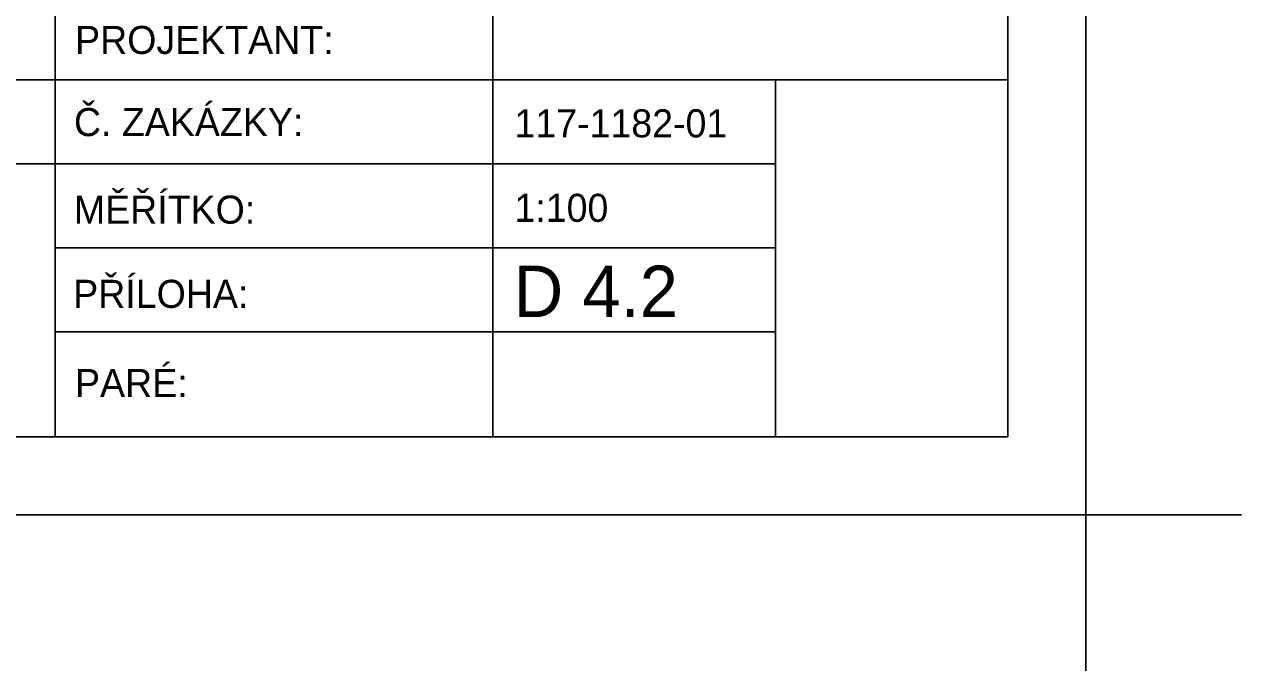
# Model space of a CAD drawing. Extents: x -552501 to -552394, y -1029983 to -1029892.
# Drawn here: x -552401.56 to -552393.76, y -1029953.75 to -1029949.6 of the extents above; entities that cross this region are included whole.
import ezdxf

# ---------------------------------------------------------------- set-up
doc = ezdxf.new("R2010")
doc.units = 0
doc.layers.add('FORMATY', color=7, linetype='Continuous')
doc.layers.add('rámeček', color=7, linetype='Continuous')

msp = doc.modelspace()

# ---------------------------------------------------------------- linework, layer by layer
at = {"layer": 'FORMATY'}
for p, q in [((-552394.7555, -1029951.7502), (-552394.7555, -1029953.7502)), ((-552394.7555, -1029951.7502), (-552394.7555, -1029953.7502)), ((-552395.7555, -1029952.7502), (-552393.7555, -1029952.7502)), ((-552395.7555, -1029952.7502), (-552393.7555, -1029952.7502))]:
    msp.add_line(p, q, dxfattribs=at)
at = {"layer": 'rámeček'}
for p, q in [((-552394.7555, -1029952.7502), (-552394.7555, -1029923.0502)), ((-552394.7555, -1029952.7502), (-552394.7555, -1029923.0502)), ((-552401.3656, -1029952.2502), (-552401.3656, -1029946.0951)), ((-552395.2555, -1029952.2502), (-552395.2555, -1029946.0951)), ((-552398.5584, -1029952.2502), (-552398.5584, -1029947.8023)), ((-552410.7555, -1029949.9588), (-552395.2555, -1029949.9588)), ((-552396.7451, -1029949.9588), (-552396.7451, -1029952.2502)), ((-552410.7555, -1029950.498), (-552396.7451, -1029950.498)), ((-552401.3656, -1029951.0371), (-552396.7451, -1029951.0369)), ((-552401.3656, -1029951.5762), (-552396.7451, -1029951.5762)), ((-552410.7555, -1029952.2502), (-552395.2555, -1029952.2502)), ((-552394.7555, -1029952.2502), (-552394.7555, -1029952.7502)), ((-552394.7555, -1029952.7502), (-552394.7555, -1029952.2502)), ((-552394.7555, -1029952.2502), (-552394.7555, -1029952.7502)), ((-552499.7555, -1029952.7502), (-552394.7555, -1029952.7502)), ((-552499.7555, -1029952.7502), (-552394.7555, -1029952.7502)), ((-552499.7555, -1029952.7502), (-552394.7555, -1029952.7502)), ((-552394.7555, -1029952.7502), (-552395.2555, -1029952.7502)), ((-552395.2555, -1029952.7502), (-552394.7555, -1029952.7502)), ((-552395.2555, -1029952.7502), (-552394.7555, -1029952.7502))]:
    msp.add_line(p, q, dxfattribs=at)

# ---------------------------------------------------------------- texts
for s, height, p in [('PROJEKTANT:', 0.18, (-552401.2384, -1029949.7926)), ('Č. ZAKÁZKY:', 0.18, (-552401.2456, -1029950.3198)), ('117-1182-01', 0.18, (-552398.42, -1029950.3277)), ('MĚŘÍTKO:', 0.18, (-552401.2462, -1029950.8814)), ('1:100', 0.18, (-552398.42, -1029950.87)), ('PŘÍLOHA:', 0.18, (-552401.2504, -1029951.422)), ('D 4.2', 0.33, (-552398.4259, -1029951.4806)), ('PARÉ:', 0.18, (-552401.2388, -1029951.9943))]:
    msp.add_text(s, height=height, rotation=0, dxfattribs=at).set_placement(p)

doc.saveas('drawing.dxf')
